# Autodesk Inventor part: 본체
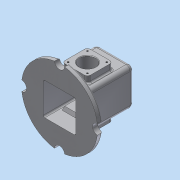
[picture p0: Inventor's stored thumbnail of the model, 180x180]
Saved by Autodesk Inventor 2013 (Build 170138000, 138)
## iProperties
Created: 2018-07
Part Number: 본체
Material: 알루미늄 6061
Document SubType Name: Modeling
Designer: Administrator
Density: 2.71 g/cm^3
Mass: 931.22 g
Surface Area: 1021.53 cm^2
Volume: 343.623 cm^3
Author: Administrator
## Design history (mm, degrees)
sketch "스케치1"
  geometry: C1 r 75 at (0, 0); 1 further point
  constraints: 1 centre point, 1 coincident
  dimensions: "d0" = 150 diameter of C1
extrude "돌출1" new body sketch "스케치1" distance "d1" = 10; taper "d2" = 0 deg
fillet "모깎기1" dims "d9" = 3
sketch "스케치2"
  geometry: C1 r 10 at (0, 75); 1 further point
  constraints: 2 vertical alignment, 1 centre point, 1 other
  dimensions: "d3" = 20 diameter of C1
extrude "돌출2" cut sketch "스케치2" distance "d4" = 10; taper "d5" = 0 deg
sketch "스케치3"
  geometry: L1 (-37, 37)-(37, 37); L2 (37, 37)-(37, -37); L3 (37, -37)-(-37, -37); L4 (-37, -37)-(-37, 37); A1 r 72 centre (0, 0) between (71.393, 9.327) and (9.327, 71.393) reference; A2 r 72 centre (0, 0) between (9.327, -71.393) and (71.393, -9.327) reference; 2 further points
  constraints: 8 end point, 2 midpoint, 2 parallel, 1 horizontal, 1 horizontal alignment, 1 perpendicular, 1 vertical alignment
  dimensions: "d10" = 74 distance of L1.start L1.end; "d12" = 74 distance of L1.end L2.end
extrude "돌출3" join sketch "스케치3" distance "d13" = 100; taper "d14" = 0 deg
sketch "스케치4"
  geometry: L1 (37, 37)-(-37, 37) reference; L2 (37, -37)-(37, 37) reference; L3 (-37, 37)-(-37, -37) reference; L4 (-37, -37)-(37, -37) reference; L5 (-32, 32)-(32, 32); L6 (32, 32)-(32, -32); L7 (32, -32)-(-32, -32); L8 (-32, -32)-(-32, 32)
  constraints: 8 end point, 3 other
  dimensions: "d15" = 5 distance between parallel lines of L1 L5
extrude "돌출4" cut sketch "스케치4" distance "d16" = 105; taper "d17" = 0 deg
fillet "모깎기2" dims "d18" = 8, "d19" = 3
sketch "스케치5"
  geometry: L1 (4, 70)-(54, 70); L2 (54, 70)-(54, 20); L3 (54, 20)-(4, 20); L4 (4, 20)-(4, 70); L5 (58, 100)-(0, 100) reference; L6 (66, 0)-(66, 92) reference; L7 (38.978, -10)-(103.333, -10) reference; 4 further points
  constraints: 8 end point, 3 midpoint, 2 parallel, 1 horizontal, 1 perpendicular, 1 vertical alignment
  dimensions: "d20" = 50 distance of L1.start L1.end; "d22" = 50 distance of L1.end L2.end; "d72" = 55 distance from line of L7 point (54, 45)
extrude "돌출5" join sketch "스케치5" distance "d23" = 13; taper "d24" = 0 deg
sketch "스케치6"
  geometry: L1 (4, 80)-(54, 80) reference; L2 (54, 80)-(54, 30) reference; L3 (54, 30)-(4, 30) reference; L4 (4, 30)-(4, 80) reference; L5 (4, 80)-(54, 80); L6 (54, 80)-(54, 30); L7 (54, 30)-(4, 30); L8 (4, 30)-(4, 80); 1 further point
  constraints: 8 end point, 2 parallel, 1 horizontal, 1 perpendicular
extrude "돌출6" join sketch "스케치6" distance "d25" = 7; taper "d26" = -20 deg
sketch "스케치7"
  geometry: L1 (54, 70)-(4, 70) reference; L2 (38.978, -10)-(103.333, -10) reference; C1 r 16 at (29, 45); 2 further points
  constraints: 1 centre point, 1 midpoint, 1 vertical alignment
  dimensions: "d27" = 32 diameter of C1; "d71" = 55 distance from line of L2 C1.centre
extrude "돌출7" cut sketch "스케치7" stored distance "d28" = 7; taper "d29" = 0 deg
chamfer "모따기1" distance "d30" = 1; stored, may be unused: second distance "d31" = 2, angle "d32" = 45 deg
fillet "모깎기3" dims "d33" = 6, "d34" = 3
hole "구멍1" diameter "d37" = 3.242; stored, may be unused: countersink angle "d41" = 90 deg, drill point angle "d43" = 118 deg; dims "d35" = 10, "d36" = 10, "d38" = 8, "d39" = 4, "d40" = 2, "d42" = 10
fillet "모깎기4" dims "d47" = 3
sketch "스케치8"
  geometry: L1 (-20, 20)-(20, 20); L2 (20, 20)-(20, -20); L3 (20, -20)-(-20, -20); L4 (-20, -20)-(-20, 20); 3 further points
  constraints: 8 end point, 2 midpoint, 2 parallel, 1 horizontal, 1 horizontal alignment, 1 perpendicular, 1 vertical alignment
  dimensions: "d48" = 40 distance of L1.start L1.end; "d50" = 40 distance of L1.end L2.end
extrude "돌출8" join sketch "스케치8" distance "d51" = 7; taper "d52" = 0 deg
sketch "스케치9"
  geometry: C1 r 17.5 at (0, 0); 1 further point
  constraints: 1 centre point, 1 coincident
  dimensions: "d53" = 35 diameter of C1
extrude "돌출9" join sketch "스케치9" distance "d54" = 3; taper "d55" = 0 deg
fillet "모깎기5" dims "d56" = 3
hole "구멍2" diameter "d59" = 21; stored, may be unused: countersink angle "d63" = 90 deg, drill point angle "d65" = 0 deg; dims "d57" = 10, "d58" = 10, "d60" = 8, "d61" = 28, "d62" = 4, "d64" = 21
fillet "모깎기6" dims "d66" = 3
sketch "스케치10"
  geometry: L1 (66, -89)-(66, 0) reference; L2 (46.5, 18)-(11.5, 18) reference; 2 further points
  constraints: 1 other
  dimensions: "d67" = 37 distance from line of point (29, -12) L1; "d68" = 30 distance from line of L2 point (29, -12)
feature "엠보싱1" sketch "스케치10" dims "d69" = 0.5, "d70" = 0
node "솔리드1"
pattern_circular "원형 패턴1" dims angle "d7" = 360 deg
pattern_circular "원형 패턴2" dims angle "d45" = 360 deg
mirror "대칭1"
node "투영된 루프1"
